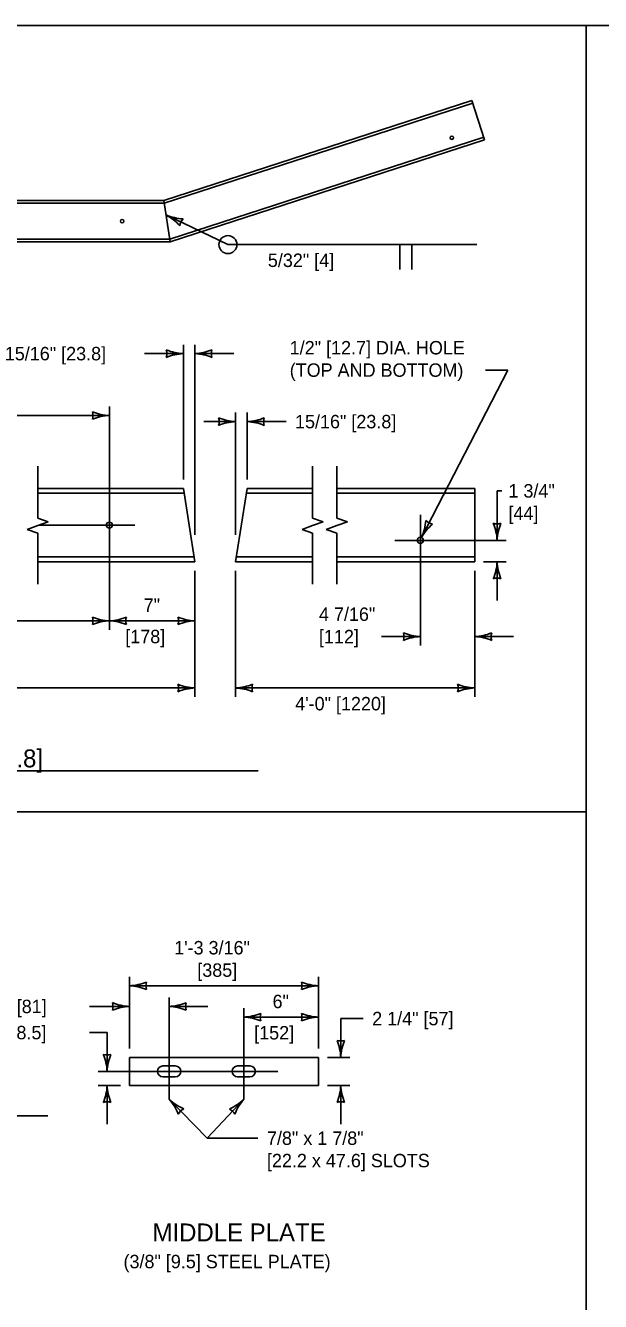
# Model space of a CAD drawing. Extents: x 49991.4 to 50021, y 49987.6 to 50011.4.
# Drawn here: x 50003.42 to 50005.99, y 49993.3 to 49999 of the extents above; entities that cross this region are included whole.
import ezdxf

# ---------------------------------------------------------------- set-up
doc = ezdxf.new("R2010")
doc.units = 0
for name, color, linetype in [('Level 1', 7, 'Continuous'), ('Level 2', 7, 'Continuous'), ('Level 3', 7, 'Continuous'), ('Level 4', 7, 'Continuous'), ('Level 5', 7, 'Continuous'), ('Level 6', 7, 'Continuous')]:
    doc.layers.add(name, color=color, linetype=linetype)

msp = doc.modelspace()

# ---------------------------------------------------------------- linework, layer by layer
at = {"layer": 'Level 1'}
for p, q in [((50005.9232, 49998.9992), (50005.9232, 49987.7988)), ((50005.4122, 49998.6642), (50004.0368, 49998.2173)), ((50005.4122, 49998.6642), (50005.4692, 49998.4888)), ((50005.4692, 49998.4888), (50004.066, 49998.0329)), ((50004.0368, 49998.2173), (49999.8398, 49998.2173)), ((50004.0368, 49998.2173), (50004.066, 49998.0329)), ((50004.0368, 49998.2173), (50004.066, 49998.0329)), ((50004.066, 49998.0329), (49999.8398, 49998.0329)), ((50004.1242, 49996.9313), (50003.4738, 49996.9313)), ((50004.1242, 49996.9313), (50004.176, 49996.6038)), ((50004.3574, 49996.6038), (50004.4092, 49996.9313)), ((50004.701, 49996.9313), (50004.4092, 49996.9313)), ((50005.4249, 49996.9313), (50004.8096, 49996.9313)), ((50005.4249, 49996.9313), (50005.4249, 49996.6038)), ((50004.176, 49996.6038), (50003.4738, 49996.6038)), ((50004.701, 49996.6038), (50004.3574, 49996.6038)), ((50005.4249, 49996.6038), (50004.8096, 49996.6038)), ((50005.9232, 49995.4868), (49999.3835, 49995.4868)), ((50004.7272, 49994.3894), (50003.8834, 49994.3894)), ((50003.8834, 49994.3894), (50003.8834, 49994.2644)), ((50004.0883, 49994.3512), (50004.0327, 49994.3512)), ((50004.4216, 49994.3512), (50004.3661, 49994.3512)), ((50004.7272, 49994.3894), (50004.7272, 49994.2644)), ((50004.0327, 49994.3026), (50004.0883, 49994.3026)), ((50004.3661, 49994.3026), (50004.4216, 49994.3026)), ((50004.7272, 49994.2644), (50003.8834, 49994.2644))]:
    msp.add_line(p, q, dxfattribs=at)
msp.add_lwpolyline([(49999.3835, 49998.9992), (50016.7501, 49998.9992), (50016.7501, 49987.7988), (49999.3835, 49987.7988)], close=True, dxfattribs=at)
for centre, radius in [((50005.3228, 49998.4978), 0.00769), ((50003.8509, 49998.1251), 0.00768), ((50003.794, 49996.7672), 0.0136), ((50005.1827, 49996.6993), 0.0137)]:
    msp.add_circle(centre, radius, dxfattribs=at)
for centre, start, end in [((50004.0327, 49994.3269), 90, 270), ((50004.0883, 49994.3269), 270, 90), ((50004.3661, 49994.3269), 90, 270), ((50004.4216, 49994.3269), 270, 90)]:
    msp.add_arc(centre, 0.0243, start, end, dxfattribs=at)
at = {"layer": 'Level 2'}
msp.add_line((50001.0295, 49995.6698), (50004.4578, 49995.6698), dxfattribs=at)
at = {"layer": 'Level 3'}
for p, q in [((50004.3233, 49998.0204), (50004.047, 49998.1531)), ((50005.4339, 49998.0204), (50004.3233, 49998.0204)), ((50005.0906, 49998.0204), (50005.0906, 49997.9089)), ((50005.1441, 49998.0204), (50005.1441, 49997.9089)), ((50004.1242, 49996.9713), (50004.1242, 49997.5734)), ((50004.176, 49996.7238), (50004.176, 49997.5734)), ((50004.1242, 49997.5334), (50003.9507, 49997.5334)), ((50004.3495, 49997.5334), (50004.176, 49997.5334)), ((50005.1871, 49996.7122), (50005.5726, 49997.4598)), ((50005.4726, 49997.4598), (50005.5726, 49997.4598)), ((50000.9451, 49997.2571), (50003.794, 49997.2571)), ((50004.3574, 49996.7238), (50004.3574, 49997.2697)), ((50004.4092, 49996.9713), (50004.4092, 49997.2697)), ((50004.2155, 49997.2297), (50004.3574, 49997.2297)), ((50004.4092, 49997.2297), (50004.5827, 49997.2297)), ((50005.5249, 49996.6993), (50005.5249, 49996.9204)), ((50005.5456, 49996.9204), (50005.5249, 49996.9204)), ((50005.4649, 49996.6038), (50005.5649, 49996.6038)), ((50005.5249, 49996.6038), (50005.5249, 49996.4303)), ((50004.176, 49996.5638), (50004.176, 49995.9997)), ((50004.3574, 49996.5638), (50004.3574, 49995.9997)), ((50005.4249, 49996.5638), (50005.4249, 49995.9997)), ((50002.8642, 49996.3397), (50003.794, 49996.3397)), ((50003.794, 49996.3397), (50004.176, 49996.3397)), ((50005.0093, 49996.2693), (50005.1827, 49996.2693)), ((50005.4249, 49996.2693), (50005.5983, 49996.2693)), ((50004.176, 49996.0397), (50000.0661, 49996.0397)), ((50005.4249, 49996.0397), (50004.3574, 49996.0397)), ((50003.8834, 49994.4294), (50003.8834, 49994.7494)), ((50004.7272, 49994.4294), (50004.7272, 49994.7494)), ((50003.8834, 49994.7094), (50004.7272, 49994.7094)), ((50003.8834, 49994.6171), (50003.7047, 49994.6171)), ((50004.234, 49994.6171), (50004.0605, 49994.6171)), ((50004.3938, 49994.5694), (50004.7272, 49994.5694)), ((50004.8272, 49994.3894), (50004.8272, 49994.5628)), ((50004.8272, 49994.5628), (50004.9272, 49994.5628)), ((50003.7835, 49994.5003), (50003.7047, 49994.5003)), ((50003.7835, 49994.3269), (50003.7835, 49994.5003)), ((50004.7672, 49994.3894), (50004.8672, 49994.3894)), ((50003.8434, 49994.2644), (50003.7435, 49994.2644)), ((50003.7835, 49994.091), (50003.7835, 49994.2644)), ((50004.7672, 49994.2644), (50004.8672, 49994.2644)), ((50004.8272, 49994.091), (50004.8272, 49994.2644)), ((50004.2308, 49994.0285), (50004.0605, 49994.2026)), ((50004.3938, 49994.2026), (50004.2308, 49994.0285)), ((50004.4574, 49994.0285), (50004.2308, 49994.0285))]:
    msp.add_line(p, q, dxfattribs=at)
msp.add_lwpolyline([(50002.4824, 49994.1283), (50003.5194, 49994.1283)], dxfattribs=at)
msp.add_circle((50004.3233, 49998.0204), 0.0401, dxfattribs=at)
for centre, radius, start, end in [((50003.9425, 49997.9568), 0.2223, 41.7971, 61.9806), ((50004.1374, 49998.3678), 0.233, 247.1684, 266.4182), ((50004.1626, 49998.0976), 0.0548, 136.4799, 172.2022), ((50004.1333, 49997.7556), 0.2223, 247.456, 267.6395), ((50003.9959, 49997.5334), 0.0548, 342.1388, 17.8612), ((50004.1645, 49997.7662), 0.233, 272.8273, 292.0772), ((50004.3042, 49997.5334), 0.0548, 162.1388, 197.8612), ((50004.1357, 49997.3007), 0.233, 92.8273, 112.0772), ((50004.1669, 49997.3113), 0.2223, 67.456, 87.6395), ((50003.8031, 49997.4792), 0.2223, 247.4558, 267.6393), ((50003.6658, 49997.2571), 0.0548, 342.1386, 17.861), ((50003.8055, 49997.0244), 0.233, 92.8271, 112.0769), ((50004.2292, 49997.2297), 0.0548, 342.1388, 17.8612), ((50004.3689, 49997.4624), 0.233, 247.9228, 267.1727), ((50004.3665, 49997.0075), 0.2223, 92.3605, 112.544), ((50004.4001, 49997.4518), 0.2223, 272.3605, 292.544), ((50004.3977, 49996.997), 0.233, 67.9228, 87.1727), ((50004.5375, 49997.2297), 0.0548, 162.1388, 197.8612), ((50004.975, 49996.8087), 0.233, 335.5495, 354.7993), ((50005.3803, 49996.6023), 0.2223, 130.1782, 150.3617), ((50005.2459, 49996.8262), 0.0548, 224.861, 260.5833), ((50005.5249, 49996.8275), 0.0548, 252.1388, 287.8612), ((50005.2922, 49996.6878), 0.233, 2.8273, 22.0772), ((50005.747, 49996.6901), 0.2223, 157.456, 177.6395), ((50005.2922, 49996.6153), 0.233, 337.9228, 357.1727), ((50005.747, 49996.6129), 0.2223, 182.3605, 202.544), ((50005.5249, 49996.4756), 0.0548, 72.1388, 107.8612), ((50003.8031, 49996.5618), 0.2223, 247.456, 267.6395), ((50003.6658, 49996.3397), 0.0548, 342.1388, 17.8612), ((50003.7825, 49996.5724), 0.233, 272.8273, 292.0772), ((50003.9222, 49996.3397), 0.0548, 162.1388, 197.8612), ((50004.1852, 49996.5618), 0.2223, 247.456, 267.6395), ((50004.0478, 49996.3397), 0.0548, 342.1388, 17.8612), ((50003.8055, 49996.107), 0.233, 92.8273, 112.0772), ((50003.7848, 49996.1175), 0.2223, 67.456, 87.6395), ((50004.1875, 49996.107), 0.233, 92.8273, 112.0772), ((50005.0545, 49996.2693), 0.0548, 342.1388, 17.8612), ((50005.1942, 49996.502), 0.233, 247.9228, 267.1727), ((50005.4157, 49996.4914), 0.2223, 272.3605, 292.544), ((50005.5531, 49996.2693), 0.0548, 162.1388, 197.8612), ((50005.1918, 49996.0471), 0.2223, 92.3605, 112.544), ((50005.4134, 49996.0366), 0.233, 67.9228, 87.1727), ((50004.1852, 49996.2618), 0.2223, 247.456, 267.6395), ((50004.0478, 49996.0397), 0.0548, 342.1388, 17.8612), ((50004.3459, 49996.2724), 0.233, 272.8273, 292.0772), ((50004.4856, 49996.0397), 0.0548, 162.1388, 197.8612), ((50005.4341, 49996.2618), 0.2223, 247.456, 267.6395), ((50005.2967, 49996.0397), 0.0548, 342.1388, 17.8612), ((50004.1875, 49995.807), 0.233, 92.8273, 112.0772), ((50004.3482, 49995.8175), 0.2223, 67.456, 87.6395), ((50005.4364, 49995.807), 0.233, 92.8273, 112.0772), ((50003.872, 49994.9421), 0.233, 272.8273, 292.0772), ((50003.8743, 49994.4873), 0.2223, 67.456, 87.6395), ((50004.0117, 49994.7094), 0.0548, 162.1388, 197.8612), ((50004.7363, 49994.9315), 0.2223, 247.456, 267.6395), ((50004.599, 49994.7094), 0.0548, 342.1388, 17.8612), ((50004.7387, 49994.4767), 0.233, 92.8273, 112.0772), ((50003.8926, 49994.8393), 0.2223, 247.456, 267.6395), ((50003.7552, 49994.6171), 0.0548, 342.1388, 17.8612), ((50004.049, 49994.8498), 0.233, 272.8273, 292.0772), ((50004.1887, 49994.6171), 0.0548, 162.1388, 197.8612), ((50003.8949, 49994.3844), 0.233, 92.8273, 112.0772), ((50004.0514, 49994.395), 0.2223, 67.456, 87.6395), ((50004.3824, 49994.8021), 0.233, 272.8273, 292.0772), ((50004.5221, 49994.5694), 0.0548, 162.1388, 197.8612), ((50004.7363, 49994.7915), 0.2223, 247.456, 267.6395), ((50004.599, 49994.5694), 0.0548, 342.1388, 17.8612), ((50004.3847, 49994.3473), 0.2223, 67.456, 87.6395), ((50004.7387, 49994.3367), 0.233, 92.8273, 112.0772), ((50004.8272, 49994.5176), 0.0548, 252.1388, 287.8612), ((50004.5944, 49994.3779), 0.233, 2.8273, 22.0772), ((50005.0493, 49994.3803), 0.2223, 157.456, 177.6395), ((50003.5613, 49994.3178), 0.2223, 2.3605, 22.544), ((50003.7835, 49994.4551), 0.0548, 252.1388, 287.8612), ((50004.0162, 49994.3154), 0.233, 157.9228, 177.1727), ((50003.5613, 49994.2736), 0.2223, 337.456, 357.6395), ((50004.0162, 49994.2759), 0.233, 182.8273, 202.0772), ((50004.5944, 49994.2759), 0.233, 337.9228, 357.1727), ((50005.0493, 49994.2736), 0.2223, 182.3605, 202.544), ((50003.7835, 49994.1362), 0.0548, 72.1388, 107.8612), ((50004.2129, 49994.3645), 0.2223, 226.7202, 246.9037), ((50003.8861, 49994.0481), 0.233, 22.2826, 41.5324), ((50004.2318, 49994.3701), 0.233, 294.8004, 314.0502), ((50004.5622, 49994.0574), 0.2223, 139.238, 159.4215), ((50004.8272, 49994.1362), 0.0548, 72.1388, 107.8612), ((50004.1502, 49994.1109), 0.0548, 116.4985, 152.2209), ((50004.3062, 49994.109), 0.0548, 29.0164, 64.7387)]:
    msp.add_arc(centre, radius, start, end, dxfattribs=at)
at = {"layer": 'Level 4'}
for p, q in [((50005.4159, 49998.6527), (50004.0387, 49998.2052)), ((50005.4654, 49998.5003), (50004.0641, 49998.045)), ((50004.0387, 49998.2052), (49999.8398, 49998.2052)), ((50004.0641, 49998.045), (49999.8398, 49998.045)), ((50004.1276, 49996.9098), (50003.4738, 49996.9098)), ((50004.701, 49996.9098), (50004.4058, 49996.9098)), ((50005.4249, 49996.9098), (50004.8096, 49996.9098)), ((50004.1726, 49996.6253), (50003.4738, 49996.6253)), ((50004.701, 49996.6253), (50004.3608, 49996.6253)), ((50005.4249, 49996.6253), (50004.8096, 49996.6253))]:
    msp.add_line(p, q, dxfattribs=at)
at = {"layer": 'Level 5'}
for p, q in [((50003.794, 49996.2997), (50003.794, 49997.2971)), ((50005.1827, 49996.2293), (50005.1827, 49996.813)), ((50003.4806, 49996.7673), (50003.9076, 49996.7673)), ((50005.069, 49996.6993), (50005.5649, 49996.6993)), ((50004.0605, 49994.6571), (50004.0605, 49994.2026)), ((50004.3938, 49994.6094), (50004.3938, 49994.2026)), ((50003.7435, 49994.3269), (50004.5459, 49994.3269))]:
    msp.add_line(p, q, dxfattribs=at)
at = {"layer": 'Level 6'}
for p, q in [((50003.4738, 49997.0313), (50003.4738, 49996.7983)), ((50004.701, 49997.0313), (50004.701, 49996.7983)), ((50004.8096, 49997.0313), (50004.8096, 49996.7983)), ((50003.4738, 49996.7983), (50003.5209, 49996.7816)), ((50004.701, 49996.7983), (50004.7482, 49996.7816)), ((50004.8096, 49996.7983), (50004.8568, 49996.7816)), ((50003.4738, 49996.7649), (50003.4267, 49996.7482)), ((50003.4267, 49996.7482), (50003.4738, 49996.7314)), ((50003.5209, 49996.7816), (50003.4738, 49996.7649)), ((50004.701, 49996.7649), (50004.6539, 49996.7482)), ((50004.6539, 49996.7482), (50004.701, 49996.7314)), ((50004.7482, 49996.7816), (50004.701, 49996.7649)), ((50004.8096, 49996.7649), (50004.7625, 49996.7482)), ((50004.7625, 49996.7482), (50004.8096, 49996.7314)), ((50004.8568, 49996.7816), (50004.8096, 49996.7649)), ((50003.4738, 49996.7314), (50003.4738, 49996.5038)), ((50004.701, 49996.7314), (50004.701, 49996.5038)), ((50004.8096, 49996.7314), (50004.8096, 49996.5038))]:
    msp.add_line(p, q, dxfattribs=at)

# ---------------------------------------------------------------- texts
at = {"layer": 'Level 2'}
for s, rotation, p in [(' 5/32" [4]', 360, (50004.4792, 49997.9204)), ('15/16" [23.8]', 360, (50003.3268, 49997.5034)), ('1/2" [12.7] DIA. HOLE', 360, (50004.599, 49997.5298)), ('(TOP AND BOTTOM)', 360, (50004.599, 49997.4298)), ('1 3/4"', 0, (50005.5756, 49996.8904)), ('[44]', 0, (50005.5756, 49996.7904)), ('4 7/16" ', 360, (50004.7297, 49996.3393)), ('[112]', 360, (50004.7297, 49996.2393)), ('4\'-0" [1220]', 0, (50004.6236, 49995.9397)), ('1\'-3 3/16"', 360, (50004.0832, 49994.8494)), (' [385]', 360, (50004.1641, 49994.7494)), ('3 3/16" [81]', 360, (50003.1063, 49994.5871)), ('6"', 360, (50004.5225, 49994.6094)), ('2 1/4" [57]', 360, (50004.9672, 49994.5328)), ('1 1/8" [28.5]', 360, (50003.0827, 49994.4703)), ('[152]', 360, (50004.4403, 49994.4694)), ('7/8" x 1 7/8"', 360, (50004.4974, 49993.9985)), ('[22.2 x 47.6] SLOTS', 360, (50004.4974, 49993.8985)), ('(3/8" [9.5] STEEL PLATE)', 360, (50003.8569, 49993.4474))]:
    msp.add_text(s, height=0.06, rotation=rotation, dxfattribs=at).set_placement(p)
for s, height, p in [('15/16" [23.8]', 0.06, (50004.6227, 49997.1997)), ('7"', 0.06, (50003.947, 49996.3797)), ('[178]', 0.06, (50003.8648, 49996.2397)), ('RUB RAIL (TS6 x 2 x 3/16) [TS152 x 51 x 4.8]', 0.08, (50001.3155, 49995.6852)), ('MIDDLE PLATE', 0.08, (50003.9865, 49993.5674))]:
    msp.add_text(s, height=height, dxfattribs=at).set_placement(p)

doc.saveas('drawing.dxf')
